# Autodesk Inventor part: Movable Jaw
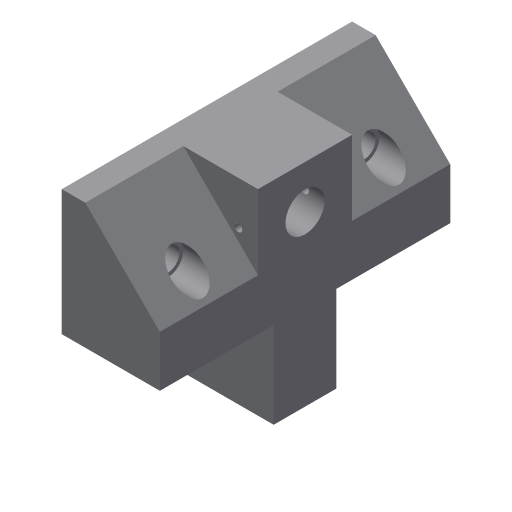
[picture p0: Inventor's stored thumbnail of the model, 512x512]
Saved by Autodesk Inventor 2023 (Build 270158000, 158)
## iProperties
Created: 2002-02
Part Number: Movable Jaw
Document SubType Name: Modeling
Designer: ***
Density: 1 g/cm^3
Material: Generic
Appearance: Default
Control State: 0
Master: False
Checked Out: False
Shininess: 77.0
Length Units: 11269
Angle Units: 11279
Time Units: 11290
Mass Units: 11283
Length Display Precision: 3
Angle Display Precision: 2
Density: 0.0
Volumn: 0.0
Area: 0.0
PropertySet Name: Model Information
Author: ***
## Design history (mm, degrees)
sketch "Sketch2"
  geometry: L1 (2.39, 41.509)-(2.39, 9.509); L2 (2.39, 9.509)-(-22.61, 9.509); L3 (-22.61, 9.509)-(-22.61, 22.509); L4 (-22.61, 22.509)-(-3.61, 41.509); L5 (-3.61, 41.509)-(2.39, 41.509)
  constraints: 10 end point, 2 parallel, 1 perpendicular, 1 vertical
  dimensions: "d0" = 25 distance of L1.end L2.end; "d2" = 13 distance of L2.end L3.end; "d3" = 32 distance between parallel lines of L5 L2; "d4" = 6 distance of L4.end L1.start
extrude "Extrusion1" new body sketch "Sketch2" stored distance "d5" = 74; taper "d6" = 0 deg
sketch "Sketch3"
  geometry: L1 (-19, 25)-(11, 25); L2 (11, 25)-(11, 49); L3 (11, 49)-(-19, 49); L4 (-19, 49)-(-19, 25); L5 (0, 0)-(13, 0) reference; L6 (-19, 74)-(-19, 0) reference; L7 (11.924, 29)-(35, 29); L8 (35, 29)-(35, 45); L9 (35, 45)-(11.924, 45); L10 (11.924, 45)-(11.924, 29); L11 (13, 74)-(13, 0) reference
  constraints: 16 end point, 4 parallel, 2 horizontal, 2 perpendicular, 1 collinear
  dimensions: "d7" = 24 distance of L3.end L1.start; "d8" = 30 distance of L1.start L1.end; "d9" = 25 distance between parallel lines of L5 L1; "d10" = 16 distance of L7.end L8.end; "d11" = 4 distance between parallel lines of L3 L9; "d12" = 22 distance between parallel lines of L11 L8
extrude "Extrusion2" join sketch "Sketch3" distance "d13" = 25; taper "d14" = 0 deg
sketch "Sketch4"
  geometry: L1 (-19, -25)-(-19, -49) reference; L2 (-19, -49)-(0, -49) reference; 1 further point
  dimensions: "d15" = 11 distance from line of L1 point (-8, -37); "d16" = 12 distance from line of L2 point (-8, -37)
hole "Hole1" sketch "Sketch4" at (-8, -37) diameter "d17" = 10; stored, may be unused: countersink angle "d21" = 82 deg, drill point angle "d23" = 0 deg; dims "d18" = 6, "d19" = 4, "d20" = 2, "d22" = 13
sketch "Sketch5"
  geometry: L1 (-19, -49)-(-19, -74) reference; L2 (0, -74)-(13, -74) reference; 1 further point
  dimensions: "d24" = 14 distance from line of L1 point (-5, -62); "d25" = 12 distance from line of L2 point (-5, -62)
hole "Hole2" sketch "Sketch5" at (-5, -62) diameter "d26" = 6; stored, may be unused: countersink angle "d30" = 82 deg, drill point angle "d32" = 0 deg; dims "d27" = 6, "d28" = 8, "d29" = 10, "d31" = 13
mirror "Mirror1"
sketch "Sketch6"
  geometry: L1 (0, 19)-(0, 0) reference; 1 further point
  dimensions: "d33" = 5 distance from line of L1 point (-5, 8); "d34" = 11 vertical distance of L1.start point (-5, 8)
hole "Hole3" sketch "Sketch6" at (-5, 8) diameter "d35" = 2; stored, may be unused: countersink angle "d39" = 82 deg, drill point angle "d41" = 0 deg; dims "d36" = 6, "d37" = 8, "d38" = 10, "d40" = 13
body "Solid1"
